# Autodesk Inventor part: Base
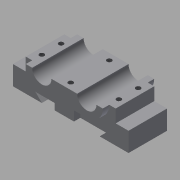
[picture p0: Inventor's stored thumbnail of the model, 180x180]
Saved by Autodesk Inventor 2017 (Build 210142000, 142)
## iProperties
Shininess: 77.0
Length Units: 11269
Angle Units: 11279
Time Units: 11290
Mass Units: 11283
Length Display Precision: 3
Angle Display Precision: 2
Created: 2002-02
Part Number: Base
Document SubType Name: Modeling
Designer: ***
Density: 1 g/cm^3
Material: Generic
Appearance: Default
Density: 0.0
Volumn: 0.0
Area: 0.0
PropertySet Name: Model Information
Control State: 0
Master: False
Checked Out: False
Author: ***
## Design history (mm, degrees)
sketch "Sketch2"
  geometry: L1 (-10.066, -1.263)-(24.934, -1.263); L2 (37.434, 11.237)-(32.434, 11.237); L3 (17.434, 11.237)-(-2.566, 11.237); L4 (-17.566, 11.237)-(-22.566, 11.237); A1 r 12.5 centre (-10.066, 11.237) between (-22.566, 11.237) and (-10.066, -1.263); A2 r 12.5 centre (24.934, 11.237) between (24.934, -1.263) and (37.434, 11.237); A3 r 7.5 centre (24.934, 11.237) between (17.434, 11.237) and (32.434, 11.237); A4 r 7.5 centre (-10.066, 11.237) between (-17.566, 11.237) and (-2.566, 11.237)
  constraints: 8 end point, 8 point on circle, 4 centre point, 3 horizontal, 3 parallel, 2 coincident, 2 equal radius, 2 tangent
  dimensions: "d0" = 12.5 radius of A1; "d1" = 7.5 radius of A4; "d2" = 35 distance of A1.centre A2.centre; "d3" = 12.5 distance between parallel lines of L3 L1
extrude "Extrusion1" new body sketch "Sketch2" stored distance "d4" = 40; taper "d5" = 0 deg
sketch "Sketch4"
  geometry: L1 (-27.566, 1.237)-(-37.566, 1.237); L2 (-37.566, 1.237)-(-37.566, -13.763); L3 (-37.566, -13.763)-(-15.066, -13.763); L4 (-15.066, -13.763)-(-20.066, -8.763); L5 (-20.066, -8.763)-(34.934, -8.763); L6 (34.934, -8.763)-(29.934, -13.763); L7 (29.934, -13.763)-(52.434, -13.763); L8 (52.434, -13.763)-(52.434, 1.237); L9 (52.434, 1.237)-(42.434, 1.237); L10 (24.934, -1.263)-(-10.066, -1.263); L11 (-17.566, 11.237)-(-22.566, 11.237) reference; L12 (37.434, 11.237)-(32.434, 11.237) reference; L13 (-22.566, 11.237)-(-27.566, 11.237); L14 (-27.566, 11.237)-(-27.566, 1.237); L15 (37.434, 11.237)-(42.434, 11.237); L16 (42.434, 11.237)-(42.434, 1.237); A1 r 12.5 centre (24.934, 11.237) between (24.934, -1.263) and (37.434, 11.237); A2 r 12.5 centre (-10.066, 11.237) between (-22.566, 11.237) and (-10.066, -1.263); A3 r 12.5 centre (24.934, 11.237) between (24.934, -1.263) and (37.434, 11.237) reference; A4 r 12.5 centre (-10.066, 11.237) between (-22.566, 11.237) and (-10.066, -1.263) reference
  constraints: 28 end point, 6 perpendicular, 5 equal length, 4 concentric, 4 parallel, 4 point on circle, 2 centre point, 2 collinear, 1 tangent
  dimensions: "d12" = 15 distance of L1.end L2.end; "d13" = 25 distance from line of L3 L11.end; "d14" = 90 distance between parallel lines of L2 L8; "d15" = 5 distance between parallel lines of L5 L7; "d16" = 22.5 distance of L2.end L3.end; "d24" = 5 distance of L12.start L15.end; "d25" = 15 distance from line of L8 L12.start
extrude "Extrusion3" join sketch "Sketch4" stored distance "d17" = 30; taper "d18" = 0 deg
sketch "Sketch5"
  geometry: L1 (-14.934, -1.263)-(0.066, -1.263); L2 (0.066, -1.263)-(0.066, -8.763); L3 (0.066, -8.763)-(-14.934, -8.763); L4 (-14.934, -8.763)-(-14.934, -1.263); L5 (10.066, -1.263)-(-24.934, -1.263) reference; 1 further point
  constraints: 8 end point, 2 parallel, 1 collinear, 1 horizontal, 1 perpendicular
  dimensions: "d19" = 7.5 distance of L1.end L2.end; "d20" = 15 distance of L2.end L3.end; "d21" = 15 distance from line of point (-29.934, -13.763) L4
extrude "Extrusion4" join sketch "Sketch5" distance "d22" = 40; taper "d23" = 0 deg
sketch "Sketch6"
  geometry: L1 (-5, -35)-(0, -35) reference; L2 (-5, -35)-(-5, -5) reference; 1 further point
  dimensions: "d26" = 7.5 distance from line of L1 point (0, -27.5); "d27" = 5 distance from line of L2 point (0, -27.5)
hole "Hole1" sketch "Sketch6" at (0, -27.5) diameter "d28" = 3.688; stored, may be unused: countersink angle "d32" = 82 deg, drill point angle "d34" = 0 deg; dims "d29" = 9, "d30" = 4, "d31" = 2, "d33" = 13
pattern_linear "Rectangular Pattern1" dims "d37" = 60, "d40" = 15
sketch "Sketch7"
  geometry: L1 (-20, -40)-(-20, -35) reference; L2 (0, -40)-(20, -40) reference; 1 further point
  dimensions: "d41" = 30 distance from line of L1 point (10, -35); "d42" = 5 distance from line of L2 point (10, -35)
hole "Hole2" sketch "Sketch7" at (10, -35) diameter "d43" = 3.688; stored, may be unused: countersink angle "d47" = 82 deg, drill point angle "d49" = 0 deg; dims "d44" = 9, "d45" = 4, "d46" = 2, "d48" = 15
pattern_linear "Rectangular Pattern2" dims "d52" = 30
body "Solid1"
